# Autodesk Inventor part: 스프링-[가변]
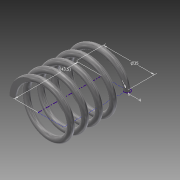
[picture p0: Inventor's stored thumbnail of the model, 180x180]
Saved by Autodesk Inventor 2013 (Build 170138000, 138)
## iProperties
Created: 2015-03
Part Number: 스프링-[가변]
Material: 강철, 탄소
Document SubType Name: Modeling
Designer: Administrator
Density: 7.87 g/cm^3
Mass: 48.1117 g
Surface Area: 61.9996 cm^2
Volume: 6.11331 cm^3
Author: Administrator
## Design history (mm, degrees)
sketch "스케치1"
  geometry: L1 (0, 0)-(17.5, 0); L2 (17.5, 0)-(17.5, -43.5); L3 (17.5, -43.5)-(0, -43.5); L4 (0, -43.5)-(0, 0); C1 r 2 at (17.5, 0)
  constraints: 8 end point, 2 parallel, 1 centre point, 1 coincident, 1 horizontal, 1 perpendicular
  dimensions: "d0" = 43.5 distance of L3.end L1.start (derived); "d1" = 35 diameter of L2 L4; "d2" = 4 diameter of C1
feature "코일1" sketch "스케치1" pitch "d3" = 10; turns "d5" = 4.5; dims "d4" = 43.5 (= d0), "d6" = 0, angle "d7" = 90 deg, angle "d8" = 90 deg, "d9" = 0, "d10" = 0
node "작업 평면1"
sketch "스케치2"
  geometry: L1 (-15.5, 0)-(-19.5, 0) reference; 1 further point
  constraints: 1 horizontal alignment
extrude "돌출1" cut sketch "스케치2" stored distance "d12" = 10; taper "d13" = 0 deg
node "작업 평면2"
sketch "스케치3"
  geometry: L1 (-19.5, 0)-(-15.5, 0) reference; 1 further point
  constraints: 1 horizontal alignment
extrude "돌출2" cut sketch "스케치3" stored distance "d15" = 10; taper "d16" = 0 deg
node "솔리드1"
node "절단 모서리 투영1"
node "절단 모서리 투영2"
other parameters: "d11" = 0, "d14" = -43.5 (= -d0)
